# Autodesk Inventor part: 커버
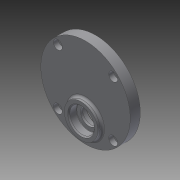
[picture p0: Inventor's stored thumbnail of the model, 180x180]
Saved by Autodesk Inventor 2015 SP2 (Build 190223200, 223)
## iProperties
Created: 2015-06
Part Number: 커버
Material: 일반
Document SubType Name: Modeling
Designer: AMC
Density: 1 g/cm^3
Appearance: 기본값
Author: AMC
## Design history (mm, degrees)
sketch "스케치1"
  geometry: C1 r 40 at (0, 0); 1 further point
  constraints: 1 centre point, 1 coincident
  dimensions: "d0" = 80 diameter of C1
extrude "돌출1" new body sketch "스케치1" distance "d1" = 9; taper "d2" = 0 deg
sketch "스케치2"
  geometry: C1 r 40 at (0, 0) reference; C2 r 15 at (0, -20); 2 further points
  constraints: 1 centre point, 1 coincident, 1 vertical alignment
  dimensions: "d4" = 30 diameter of C2; "d7" = 20 distance of C2.centre point (0, 0)
extrude "돌출2" join sketch "스케치2" distance "d5" = 4; taper "d6" = 0 deg
sketch "스케치3"
  geometry: C1 r 14 at (0, -11); C2 r 14 at (0, 20); 1 further point
  constraints: 2 centre point, 2 vertical alignment
  dimensions: "d8" = 28 diameter of C1; "d9" = 28 diameter of C2; "d10" = 20 distance of C2.centre point (0, 0); "d11" = 11 distance of point (0, 0) C1.centre
extrude "돌출3" join sketch "스케치3" distance "d12" = 3; taper "d13" = 0 deg
hole "구멍1" diameter "d16" = 15; stored, may be unused: countersink angle "d20" = 90 deg, drill point angle "d22" = 118 deg; dims "d14" = 10, "d15" = 10, "d17" = 6, "d18" = 22, "d19" = 7, "d21" = 8
hole "구멍2" diameter "d25" = 15; stored, may be unused: countersink angle "d29" = 90 deg, drill point angle "d31" = 118 deg; dims "d23" = 10, "d24" = 10, "d26" = 6, "d27" = 22, "d28" = 7, "d30" = 8
hole "구멍3" diameter "d34" = 18; stored, may be unused: countersink angle "d38" = 90 deg, drill point angle "d40" = 0 deg; dims "d35" = 6, "d36" = 22, "d37" = 7, "d39" = 8, "d41" = 10, "d42" = 10
sketch "스케치7"
  geometry: L1 (0, 0)-(0, 15.131); L2 (0, 0)-(24.749, 24.749); L3 (0, 0)-(35, 0); 1 further point
  constraints: 6 end point, 1 coincident, 1 equal length, 1 horizontal, 1 vertical
  dimensions: "d51" = 35 distance of L1.start L2.end; "d52" = 45 deg angle of L3 L2
hole "구멍4" sketch "스케치7" at (24.749, 24.749) diameter "d53" = 4.5; stored, may be unused: countersink angle "d57" = 90 deg, drill point angle "d59" = 0 deg; dims "d54" = 6, "d55" = 8, "d56" = 4.4, "d58" = 8
fillet "모깎기1" dims "d63" = 2
chamfer "모따기1" distance "d64" = 1; stored, may be unused: second distance "d65" = 2, angle "d66" = 45 deg
fillet "모깎기2" dims "d67" = 0.3
chamfer "모따기2" distance "d68" = 1; stored, may be unused: second distance "d69" = 2, angle "d70" = 45 deg
node "솔리드1"
pattern_circular "원형 패턴1" dims angle "d61" = 360 deg
